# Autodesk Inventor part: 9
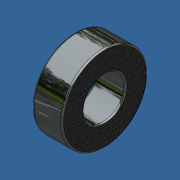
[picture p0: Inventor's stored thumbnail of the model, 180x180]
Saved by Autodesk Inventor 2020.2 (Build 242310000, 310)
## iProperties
Created: 2016-09
Part Number: 9
Material: Steel
Document SubType Name: Modeling
Designer: Mike Taylor
Mass: 229.906 g
Surface Area: 74.1228 cm^2
Volume: 29.2873 cm^3
Density: 7.85 g/cm^3
Appearance: Plate
Translation Standard: STEP AP214IS
FileName: 29_5060_0_1.stp
PreProcessor: ACIS
PostProcessor: Build: 160, Release: 2012 RTM - Date: Tue 03/01/2011
Sent Units: centimeter
Uncertainty: 0.0
Author: Mike Taylor
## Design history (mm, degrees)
node "91"
node "9"
node "Base1"
